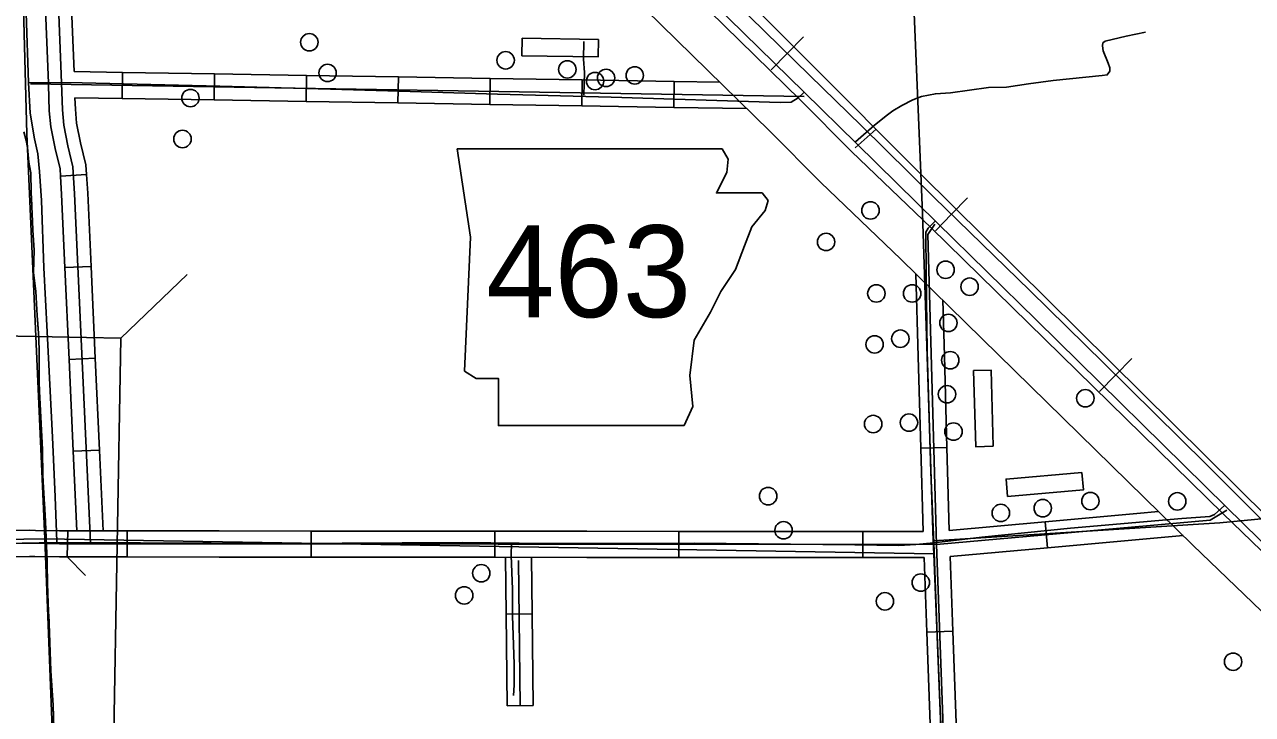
# Model space of a CAD drawing. Extents: x 646058 to 725608, y 1473014 to 1561048.
# Drawn here: x 655499 to 659024, y 1544485 to 1546468 of the extents above; entities that cross this region are included whole.
import ezdxf

# ---------------------------------------------------------------- set-up
doc = ezdxf.new("R2010")
doc.units = 0
doc.layers.add('Default', color=7, linetype='Continuous')

msp = doc.modelspace()

# ---------------------------------------------------------------- linework, layer by layer
at = {"layer": 'Default'}
for p, q in [((657688.3, 1546384.8), (657734.5, 1546431.9)), ((657688.3, 1546384.8), (657642.1, 1546337.6)), ((655778.7, 1546255.1), (655779.9, 1546330.1)), ((656042.6, 1546250.9), (656043.8, 1546325.9)), ((656306.6, 1546246.6), (656307.8, 1546321.6)), ((656570.5, 1546242.3), (656571.8, 1546317.3)), ((656834.5, 1546238.1), (656835.7, 1546313.1)), ((657098.5, 1546233.8), (657099.7, 1546308.8)), ((657362.4, 1546229.6), (657363.7, 1546304.5)), ((655676.5, 1546036.9), (655601.7, 1546032.3)), ((658159.3, 1545922.4), (658205.4, 1545969.8)), ((658159.3, 1545922.4), (658113.3, 1545875.1)), ((655689.4, 1545772.6), (655614.5, 1545769.2)), ((655775.4, 1545566.5), (655965.5, 1545749.7)), ((655701.5, 1545508.9), (655626.5, 1545505.4)), ((658630.8, 1545460.6), (658677.1, 1545507.7)), ((658630.8, 1545460.6), (658584.5, 1545413.6)), ((655713.5, 1545245.1), (655638.6, 1545241.7)), ((658146.7, 1545252.3), (658071.7, 1545250.2)), ((658435.1, 1544964.3), (658428.4, 1545039)), ((655622.4, 1545013.1), (655621, 1544938.1)), ((655793, 1545013), (655793, 1544938)), ((656321, 1544937.5), (656321, 1545012.5)), ((656849, 1545012.1), (656849, 1544937.1)), ((657377, 1544936.6), (657377, 1545011.6)), ((657905, 1545011.2), (657905, 1544936.2)), ((656321, 1544937.5), (656321, 1544937.5)), ((656955.9, 1544774.8), (656881, 1544773.8)), ((658088.6, 1544722.1), (658163.6, 1544724.9)), ((656959.2, 1544510.8), (656884.2, 1544509.9))]:
    msp.add_line(p, q, dxfattribs=at)
for points in [[(660168.2, 1543949.1), (659919.8, 1544195.1), (659588.3, 1544516.1), (659439.9, 1544664.5), (659227.9, 1544873.5), (659088.6, 1545006.7), (658890.3, 1545205.1), (658596.6, 1545494.3), (658384.6, 1545703.3), (658109.1, 1545971.3), (657900.1, 1546177.3), (657753.3, 1546321.1), (657536.8, 1546533.1), (657293, 1546773.9), (657050.8, 1547016.2), (656776.7, 1547278.1), (656548.1, 1547505.3), (656345.2, 1547702.1), (656118.1, 1547924.7), (656003.1, 1548039), (655996.2, 1548045.9), (655880.4, 1548161), (655686.6, 1548351.8)], [(660168.2, 1543949.1), (659919.8, 1544195.1), (659588.3, 1544516.1), (659439.9, 1544664.5), (659227.9, 1544873.5), (659088.6, 1545006.7), (658890.3, 1545205.1), (658596.6, 1545494.3), (658384.6, 1545703.3), (658109.1, 1545971.3), (657900.1, 1546177.3), (657753.3, 1546321.1), (657536.8, 1546533.1), (657293, 1546773.9), (657050.8, 1547016.2), (656776.7, 1547278.1), (656548.1, 1547505.3), (656345.2, 1547702.1), (656118.1, 1547924.7), (656003.1, 1548039)], [(658000, 1547762.6), (658076.8, 1545925.9), (658107.4, 1544984.1), (658108.9, 1544947.2), (658148.7, 1543949.1)], [(656285.3, 1547699.2), (656498.5, 1547488.2), (656606.3, 1547382.3), (656654.9, 1547334.4), (656655.1, 1547334.2), (657032.8, 1546963.4), (657077.8, 1546920.2), (657390.5, 1546613.2), (657736.4, 1546273.5)], [(656285.3, 1547699.2), (656498.5, 1547488.2), (656606.3, 1547382.3), (656654.9, 1547334.4), (656655.1, 1547334.2), (657032.8, 1546963.4), (657077.8, 1546920.2), (657390.5, 1546613.2), (657736.4, 1546273.5)], [(656285.3, 1547699.2), (656498.5, 1547488.2), (656606.3, 1547382.3), (656654.9, 1547334.4), (656655.1, 1547334.2), (657032.8, 1546963.4), (657077.8, 1546920.2), (657390.5, 1546613.2), (657736.4, 1546273.5)], [(656285.3, 1547699.2), (656498.5, 1547488.2), (656606.3, 1547382.3), (656654.9, 1547334.4), (656655.1, 1547334.2), (657032.8, 1546963.4), (657077.8, 1546920.2), (657390.5, 1546613.2), (657736.4, 1546273.5)], [(656425.6, 1547675.7), (657430.5, 1546682.8), (658072.2, 1546037.3), (659069.6, 1545049.8)], [(655509.6, 1546301.3), (655496.8, 1546700.7), (655483.2, 1547012), (655473.3, 1547247.4), (655462.4, 1547512.5), (655457, 1547653.3)], [(655556.4, 1544989.8), (655505.1, 1546154.1), (655464.9, 1547665)], [(655688.1, 1544979.7), (655642.4, 1545980.9), (655637.6, 1546058.9), (655622.6, 1546119.3), (655610.9, 1546178.6), (655607.1, 1546222.5), (655604.4, 1546300.1), (655552, 1547650.2)], [(657050.8, 1547016.2), (657293, 1546773.9), (657536.8, 1546533.1), (657753.3, 1546321.1), (657900.1, 1546177.3), (658109.1, 1545971.3), (658384.6, 1545703.3), (658596.6, 1545494.3), (658890.3, 1545205.1), (659088.6, 1545006.7), (659227.9, 1544873.5), (659439.9, 1544664.5), (659588.3, 1544516.1), (659919.8, 1544195.1), (660168.2, 1543949.1)], [(656984.6, 1546977.7), (657726.5, 1546250.4), (657872.6, 1546102.8), (658101.1, 1545883.7), (658939.4, 1545061.8), (659185.2, 1544824.5), (659858.4, 1544165.7)], [(659775.5, 1544072), (659098.1, 1544734.9), (658852.2, 1544972.2), (658014.1, 1545794), (657784.9, 1546013.7), (657638.3, 1546161.8), (656924.6, 1546861.4)], [(655567.1, 1546294.1), (655567, 1546298.8), (655556.9, 1546557.7)], [(655640.7, 1546332.4), (655631.8, 1546560.6)], [(658716.8, 1546446.1), (658661.4, 1546434.4), (658600.5, 1546419.6), (658594.3, 1546414.7), (658593.1, 1546406.7), (658595, 1546392.6), (658609.7, 1546356.8), (658614.7, 1546343.3), (658614, 1546333.4), (658606.7, 1546323), (658592.5, 1546321.1), (658451.5, 1546307), (658380.8, 1546297.7), (658317.4, 1546287.9), (658266.3, 1546286.7), (658156.7, 1546271.9), (658113.6, 1546268.8), (658073.6, 1546260.8), (658049, 1546251.6), (658017, 1546235.5), (657991.7, 1546220.2), (657972, 1546205.4), (657933.9, 1546174.6)], [(658716.8, 1546446.1), (658661.4, 1546434.4), (658600.5, 1546419.6), (658594.3, 1546414.7), (658593.1, 1546406.7), (658595, 1546392.6), (658609.7, 1546356.8), (658614.7, 1546343.3), (658614, 1546333.4), (658606.7, 1546323), (658592.5, 1546321.1), (658451.5, 1546307), (658380.8, 1546297.7), (658317.4, 1546287.9), (658266.3, 1546286.7), (658156.7, 1546271.9), (658113.6, 1546268.8), (658073.6, 1546260.8), (658049, 1546251.6), (658017, 1546235.5), (657991.7, 1546220.2), (657972, 1546205.4), (657937.5, 1546177.5)], [(657104.1, 1546419.2), (657103.2, 1546368.6), (657105.9, 1546329.6), (657104.1, 1546264.5)], [(655640.7, 1546332.4), (655779.9, 1546330.1)], [(655509.6, 1546301.3), (655514.8, 1546213), (655527.3, 1546138.9), (655536.8, 1546096.4), (655541.9, 1546045), (655547.1, 1545962.1), (655553.7, 1545768.4), (655563.2, 1545585), (655578.6, 1545282), (655586.7, 1545111.1), (655590.4, 1545009.1), (655591.1, 1544981.2)], [(655509.6, 1546301.3), (655664.2, 1546299.8), (656059.6, 1546290.7), (656377.2, 1546281.7), (656573.6, 1546276.2), (656855.9, 1546267.2), (657182.6, 1546259), (657667.6, 1546243.7), (657699.2, 1546244.6), (657719.1, 1546257.2), (657735.4, 1546272.6)], [(655515.3, 1546296.9), (657737, 1546261)], [(655779.9, 1546330.1), (656043.8, 1546325.9)], [(656043.8, 1546325.9), (656307.8, 1546321.6)], [(656307.8, 1546321.6), (656571.8, 1546317.3)], [(656571.8, 1546317.3), (656835.7, 1546313.1)], [(656835.7, 1546313.1), (657099.7, 1546308.8)], [(657099.7, 1546308.8), (657363.7, 1546304.5)], [(657363.7, 1546304.5), (657494.8, 1546302.4)], [(655601.7, 1546032.3), (655600.4, 1546053.2), (655586, 1546111.2), (655573.7, 1546173.4), (655569.6, 1546220.2), (655567.1, 1546294.1)], [(657736.4, 1546273.5), (657886.9, 1546125.7)], [(657736.4, 1546273.5), (657886.9, 1546125.7)], [(657736.4, 1546273.5), (657886.9, 1546125.7)], [(657736.4, 1546273.5), (657886.9, 1546125.7)], [(655643.4, 1546257.3), (655778.7, 1546255.1)], [(655676.5, 1546036.9), (655674.8, 1546064.6), (655659.2, 1546127.5), (655648, 1546183.9), (655644.5, 1546224.7), (655643.4, 1546257.3)], [(655778.7, 1546255.1), (656042.6, 1546250.9)], [(656042.6, 1546250.9), (656306.6, 1546246.6)], [(656306.6, 1546246.6), (656570.5, 1546242.3)], [(656570.5, 1546242.3), (656834.5, 1546238.1)], [(656834.5, 1546238.1), (657098.5, 1546233.8)], [(657098.5, 1546233.8), (657362.4, 1546229.6)], [(657362.4, 1546229.6), (657572.6, 1546226.2)], [(655496.6, 1546159), (655503.7, 1546134.1), (655506.8, 1546114.8), (655510.8, 1546072.7), (655516.4, 1546041.2), (655517.9, 1545985.3), (655521.5, 1545903.1), (655522, 1545876.7), (655526.6, 1545819.8), (655524.5, 1545754.8), (655530.6, 1545700.5), (655535.2, 1545631.4), (655539.8, 1545567.4), (655540.3, 1545524.8), (655540.8, 1545432.4), (655549.9, 1545247.1), (655551.4, 1545169.9), (655558.5, 1545039.9), (655558.6, 1545037.9)], [(655496.6, 1546159), (655503.7, 1546134.1), (655506.8, 1546114.8), (655510.8, 1546072.7), (655516.4, 1546041.2), (655517.9, 1545985.3), (655521.5, 1545903.1), (655522, 1545876.7), (655526.6, 1545819.8), (655524.5, 1545754.8), (655530.6, 1545700.5), (655535.2, 1545631.4), (655539.8, 1545567.4), (655540.3, 1545524.8), (655540.8, 1545432.4), (655549.9, 1545247.1), (655551.4, 1545169.9), (655558.5, 1545039.9), (655563.1, 1544925.1), (655564.6, 1544856.1), (655574.3, 1544610.9), (655580.4, 1544512.4), (655585.4, 1544345.8)], [(657883.1, 1546113.5), (657943.2, 1546167.1)], [(657937.5, 1546177.5), (657884, 1546130.3)], [(655500.4, 1546145.7), (655503.7, 1546134.1), (655506.8, 1546114.8), (655510.8, 1546072.7), (655516.4, 1546041.2), (655517.9, 1545985.3), (655519.5, 1545949.1)], [(657886.9, 1546125.7), (658118.5, 1545898.2)], [(657886.9, 1546125.7), (658118.5, 1545898.2)], [(657886.9, 1546125.7), (658118.5, 1545898.2)], [(657886.9, 1546125.7), (658118.5, 1545898.2)], [(655614.5, 1545769.2), (655604.9, 1545978.9), (655601.7, 1546032.3)], [(655689.4, 1545772.6), (655679.8, 1545982.9), (655676.5, 1546036.9)], [(655521.9, 1545883.1), (655522, 1545876.7), (655526.6, 1545819.8), (655524.5, 1545754.8), (655530.6, 1545700.5), (655531.6, 1545685.7)], [(658108.7, 1544978.8), (658100.7, 1545181.9), (658090.2, 1545529.4), (658086.9, 1545752), (658086, 1545870.8), (658092.7, 1545882.5), (658113.6, 1545903.4)], [(658154.3, 1543949.1), (658117, 1544973.5), (658091.9, 1545864.9), (658111.6, 1545894.5)], [(658118.5, 1545898.2), (658403.5, 1545618.2), (658948.3, 1545082.3)], [(658118.5, 1545898.2), (658403.5, 1545618.2), (658948.3, 1545082.3)], [(658118.5, 1545898.2), (658403.5, 1545618.2), (658948.3, 1545082.3)], [(658118.5, 1545898.2), (658403.5, 1545618.2), (658948.3, 1545082.3)], [(655626.5, 1545505.4), (655614.5, 1545769.2)], [(655701.5, 1545508.9), (655689.4, 1545772.6)], [(658064.3, 1545514.1), (658057.6, 1545751.3)], [(658139.2, 1545516.2), (658134.7, 1545675.7)], [(655536, 1545619.9), (655539.8, 1545567.4), (655540.3, 1545524.8), (655540.8, 1545432.4), (655541.3, 1545422)], [(655638.6, 1545241.7), (655626.5, 1545505.4)], [(655713.5, 1545245.1), (655701.5, 1545508.9)], [(658071.7, 1545250.2), (658064.3, 1545514.1)], [(658146.7, 1545252.3), (658139.2, 1545516.2)], [(655544.5, 1545356.1), (655549.9, 1545247.1), (655551.4, 1545169.9), (655552.1, 1545158.3)], [(655649, 1545013.1), (655638.6, 1545241.7)], [(655724.1, 1545013), (655713.5, 1545245.1)], [(658071.7, 1545250.2), (658078.4, 1545011)], [(658153.3, 1545014.4), (658146.7, 1545252.3)], [(660860.6, 1545222), (658930.3, 1545036.4), (658107.4, 1544984.1)], [(655555.7, 1545092.4), (655558.5, 1545039.9), (655558.6, 1545037.9)], [(658108.7, 1544978.8), (658246.3, 1544994.7), (658501.6, 1545020.4), (658821, 1545048.2), (658901.1, 1545054.6), (658915, 1545059.9), (658943.8, 1545085.5)], [(658949.8, 1545072.6), (658902.1, 1545043.8), (658117, 1544973.5)], [(658754.3, 1545068.2), (658691.3, 1545062.6)], [(658948.3, 1545082.3), (659710.5, 1544334.3), (660100.4, 1543949.1)], [(658948.3, 1545082.3), (659710.5, 1544334.3), (660100.4, 1543949.1)], [(658948.3, 1545082.3), (659710.5, 1544334.3), (660100.4, 1543949.1)], [(658948.3, 1545082.3), (659710.5, 1544334.3), (660100.4, 1543949.1)], [(658428.4, 1545039), (658153.3, 1545014.4)], [(658691.3, 1545062.6), (658428.4, 1545039)], [(655529.7, 1545014.4), (655513.4, 1545014.7), (655264.7, 1545012.2)], [(655649, 1545013.1), (655599.3, 1545013.1), (655529.7, 1545014.4)], [(655793, 1545013), (655724.1, 1545013), (655649, 1545013.1)], [(656057, 1545012.7), (655793, 1545013)], [(656321, 1545012.5), (656057, 1545012.7)], [(656585, 1545012.3), (656321, 1545012.5)], [(656849, 1545012.1), (656585, 1545012.3)], [(657113, 1545011.8), (656849, 1545012.1)], [(657377, 1545011.6), (657113, 1545011.8)], [(657641, 1545011.4), (657377, 1545011.6)], [(657905, 1545011.2), (657641, 1545011.4)], [(658078.4, 1545011), (657905, 1545011.2)], [(658824.7, 1544999.2), (658698, 1544987.9)], [(655513.3, 1544977.2), (652908.5, 1544951.1), (652283.8, 1544936.9), (652264, 1544932.5), (652246.2, 1544927.7), (652221.6, 1544930.1), (651569.2, 1544908.6)], [(652899, 1544951.5), (653207, 1544956), (653532.5, 1544957.6), (653765.9, 1544960.1), (653984.3, 1544963.4), (654201.9, 1544964.3), (654420.3, 1544966.8), (654652, 1544968.4), (654901.9, 1544971.8), (655342.1, 1544975.1), (655590.4, 1544979.2)], [(652908.6, 1544947.9), (655556.4, 1544989.8)], [(658117, 1544973.5), (655599, 1544975.6), (655513.3, 1544977.2)], [(655556.4, 1544989.8), (658108.9, 1544947.2)], [(655596.8, 1543949.1), (655556.4, 1544989.8)], [(655590.4, 1544979.2), (655831, 1544978.8), (656237.9, 1544976.8), (656755.1, 1544979.9), (657001.3, 1544976.8), (657420.5, 1544977.8), (657882.1, 1544972.7), (658008.8, 1544970.6), (658057.2, 1544973.7), (658108.7, 1544978.8)], [(656896.4, 1544978.1), (656895.3, 1544941.8), (656899.6, 1544845.2), (656899.5, 1544768.6), (656903.9, 1544630), (656904.6, 1544569.2), (656902, 1544539.5)], [(658108.7, 1544978.8), (658117.9, 1544737.7), (658127.4, 1544500), (658140.8, 1544200.5), (658149.9, 1543949.1)], [(658155.7, 1544939.3), (658435.1, 1544964.3)], [(658698, 1544987.9), (658435.1, 1544964.3)], [(655528.3, 1544939.4), (655513.1, 1544939.7), (655265.4, 1544937.2)], [(655793, 1544938), (655598.6, 1544938.1), (655528.3, 1544939.4)], [(655562.8, 1544938.8), (655564.6, 1544856.1), (655565.3, 1544839.8)], [(655562.8, 1544938.8), (655564.6, 1544856.1), (655574.3, 1544610.9), (655580.4, 1544512.4), (655585.4, 1544345.8), (655590, 1544181.8), (655598, 1543949.1)], [(655673.5, 1544884.6), (655621, 1544938.1)], [(655793, 1544938), (656057, 1544937.7)], [(656057, 1544937.7), (656321, 1544937.5)], [(656585, 1544937.3), (656321, 1544937.5)], [(656849, 1544937.1), (656585, 1544937.3)], [(656849, 1544937.1), (657113, 1544936.8)], [(656881, 1544773.8), (656878.9, 1544937)], [(656921.7, 1544510.3), (656916.6, 1544928)], [(656955.9, 1544774.8), (656953.9, 1544937)], [(657113, 1544936.8), (657377, 1544936.6)], [(657641, 1544936.4), (657377, 1544936.6)], [(657905, 1544936.2), (657641, 1544936.4)], [(657905, 1544936.2), (658080.8, 1544936)], [(658080.8, 1544936), (658088.6, 1544722.1)], [(658163.6, 1544724.9), (658155.7, 1544939.3)], [(655567.9, 1544773.9), (655574.3, 1544610.9), (655576.4, 1544576.1)], [(656884.2, 1544509.9), (656881, 1544773.8)], [(656959.2, 1544510.8), (656955.9, 1544774.8)], [(658098.2, 1544458.3), (658088.6, 1544722.1)], [(658173.2, 1544461), (658163.6, 1544724.9)], [(655580.4, 1544510.2), (655585.4, 1544345.8), (655586.4, 1544312.3)]]:
    msp.add_lwpolyline(points, dxfattribs=at)
for points in [[(656926.6, 1546378.2), (656927.4, 1546428.2), (657146.1, 1546424.7), (657145.3, 1546374.7)], [(656740.5, 1546110.7), (656778.6, 1545856.9), (656761.6, 1545472), (656795.5, 1545450.9), (656858.9, 1545450.9), (656858.9, 1545315.5), (657391.8, 1545315.5), (657417.2, 1545370.5), (657408.8, 1545459.3), (657421.4, 1545560.8), (657468, 1545641.2), (657497.6, 1545700.4), (657539.9, 1545763.8), (657565.2, 1545831.5), (657586.4, 1545886.5), (657624.5, 1545933), (657632.9, 1545962.6), (657616, 1545983.8), (657484.9, 1545983.8), (657514.5, 1546043), (657518.7, 1546081), (657501.2, 1546110.3)], [(655753.5, 1544378.7), (655775.4, 1545566.5), (655379.4, 1545573.8), (655357.5, 1544386)], [(658279.5, 1545256.1), (658229.5, 1545254.7), (658223.3, 1545473.4), (658273.3, 1545474.8)], [(658534.3, 1545181), (658538.8, 1545131.2), (658320.9, 1545111.7), (658316.5, 1545161.5)]]:
    msp.add_lwpolyline(points, close=True, dxfattribs=at)
for centre in [(656316.2, 1546416.9), (656879.7, 1546364.9), (656368.5, 1546328.7), (657056.8, 1546338.7), (657168.1, 1546314.3), (657250.4, 1546321.5), (657136.4, 1546305.2), (655974.9, 1546256.3), (655952, 1546138.8), (657927.1, 1545933.5), (657799.7, 1545843), (658142.7, 1545763), (658211.7, 1545714.5), (657944, 1545695), (658046.7, 1545695), (658150.9, 1545610.5), (657938.9, 1545548.7), (658012.9, 1545565.1), (658156.1, 1545503.3), (658146.8, 1545405.4), (658543.9, 1545393.9), (657934.9, 1545319.9), (658037.6, 1545324), (658165.4, 1545298.3), (657633.3, 1545112.7), (658421.7, 1545078.1), (658558.4, 1545098.5), (658807.9, 1545097.7), (658301.3, 1545064.4), (657677.5, 1545014.6), (656809.7, 1544891.3), (658071.6, 1544864.5), (656760.6, 1544827.5), (657968.6, 1544810.5), (658968.2, 1544637)]:
    msp.add_circle(centre, 25, dxfattribs=at)

# ---------------------------------------------------------------- texts
msp.add_text('463', height=264, dxfattribs=at).set_placement((656823.5, 1545626.9))

doc.saveas('drawing.dxf')
